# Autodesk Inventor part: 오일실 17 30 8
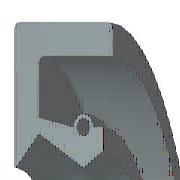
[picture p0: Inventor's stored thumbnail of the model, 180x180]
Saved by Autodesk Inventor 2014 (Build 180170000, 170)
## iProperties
Created: 2012-02
Part Number: 오일실 17 30 8
Material: 고무
Description: 오일-실
Document SubType Name: Modeling
Standard: KS B 2804
Designer: mduedu
Standards Organization: KS
Language: ko-KR
Size Designation: D - 17 30 8
Categories: <MemberInstance><Categories><Category DisplayName="샤프트 부품" InternalName="7f7aeb1f-a693-4053-b835-cee3144e0d98" Mnemonic="SHFT"><Category DisplayName="실링" Intern
Density: 0.93 g/cm^3
Appearance: 고무 - 검은색 - 버전 1.1
Mass: 2.05797 g
Surface Area: 29.3036 cm^2
Volume: 2.21288 cm^3
IsCustomPart: 1
Author: mduedu
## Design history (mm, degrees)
revolve "본체" stored, may be unused: angle "d17" = 90 deg
revolve "스프링1" stored, may be unused: angle "d18" = 90 deg
body "Solid1"
sketch "스케치1"
  geometry: L1 (0, 15)-(8, 15); L2 (8, 13.25)-(1.75, 13.25); L3 (1.75, 10.25)-(4.9, 8.5); L4 (4.9, 8.5)-(0, 8.5); L5 (0, 0)-(9.586, 0) reference; L6 (4.9, 8.5)-(6.3, 9.375); L7 (0, 18)-(0, -3) reference; L8 (-1.941, 0)-(11.507, 0) reference; L9 (4.2, 10.6)-(1.75, 11.21); L10 (1.75, 11.21)-(1.75, 13.25); L11 (0, 15)-(0, 8.588); L12 (4.9, 8.5)-(0, 8.5); L13 (1.75, 10.25)-(0.152, 8.528); L14 (8, 15)-(8, 13.25); L15 (5.6, 10.6)-(6.3, 10.6); L16 (6.3, 10.6)-(6.3, 9.375); C1 r 0.455 at (4.9, 10.6); A1 r 0.7 centre (4.9, 10.6) between (5.6, 10.6) and (4.2, 10.6); A2 r 0.088 centre (0.088, 8.588) between (0, 8.588) and (0.152, 8.528); 1 further point
  constraints: 28 end point, 5 horizontal alignment, 5 point on line, 4 point on circle, 4 vertical alignment, 3 centre point, 3 tangent, 2 collinear, 2 horizontal, 2 perpendicular, 1 coincident, 1 parallel
  dimensions: "d0" = 30 diameter of L1 L5 (= SD2); "d1" = 1.75 distance of L1.end L2.start (= SD); "d2" = 0.91 diameter of C1 (= SPDI); "d3" = 1.4 diameter of A1 (= SPDA); "d4" = 17 diameter of L3.end L5 (= NND); "d5" = 20.5 diameter of L3.start L5 (= TKDM); "d7" = 22.42 diameter of L9.end L5 (= TKDM + 0.24 x SWDT); "d8" = 1.75 distance between parallel lines of L11 L10 (= SD); "d9" = 4.9 distance from line of L11 C1.centre (= SPDST); "d10" = 21.2 diameter of C1.centre L5 (= HLDM); "d11" = 0.0875 radius of A2 (= 0.25 x LAB); "d12" = 6.3 distance between parallel lines of L11 L16 (= SDI); "d13" = 18.75 diameter of L6.end L5 (= ABDM); "d14" = 8 distance from line of L11 L1.end (= SWDT)
fillet "모깎기1" dims "d6" = 0.3 (= RR)
other parameters: "SD2" = 30 [user parameter; used in 1 equation term], "SWDT" = 8 [user parameter; used in 2 equation terms], "RR" = 0.3 [user parameter; used in 1 equation term], "SD" = 1.75 [user parameter; used in 2 equation terms], "NND" = 17 [user parameter; used in 1 equation term], "SPDA" = 1.4 [user parameter; used in 1 equation term], "SPDI" = 0.91 [user parameter; used in 1 equation term], "TKDM" = 20.5 [user parameter; used in 2 equation terms], "HLDM" = 21.2 [user parameter; used in 1 equation term], "ABDM" = 18.75 [user parameter; used in 1 equation term], "SDI" = 6.3 [user parameter; used in 1 equation term], "SPDST" = 4.9 [user parameter; used in 1 equation term], "LAB" = 0.35 [user parameter; used in 1 equation term], "d15" = 0, "d16" = 0, "d19" = 0
